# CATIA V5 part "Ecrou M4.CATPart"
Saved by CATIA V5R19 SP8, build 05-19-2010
Part number: Nut M4
Definition: Nut M4
Nomenclature: 71002
Material "Chrome": density 7190 kg/m3, Young's modulus 7e+10 Pa, Poisson ratio 0.3, thermal expansion 6.2e-06 1/K
Bounding box of the stored display mesh (mm): x -4.041 to 4.041, y -3.525 to 3.525, z 0 to 3.2
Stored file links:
  D:\Documents\1_Travail\1 - ac-limoges.fr\ac-limoges.fr\Emmanuel Maynard - STI2D_Turgot\1 - IT-I2D\Activités_IT_Première\IT_3_Abris_bus\Maquettes numériques\Abribus_eleve\Ecrou M4.CATPart
  C:\Program Files\Dassault Systemes\B19\win_b64\reffiles\standard\MetricThickPitch.txt
  C:\Program Files\Dassault Systemes\B19\win_b64\startup\materials\French\Catalog.CATMaterial
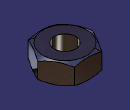
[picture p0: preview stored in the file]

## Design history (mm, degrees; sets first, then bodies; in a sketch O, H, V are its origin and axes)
AxisSystem1: origin (0, 0, 0), X (1, 0, 0), Y (0, 1, 0), Z (0, 0, 1)
Body1 (main body), material "Chrome"
  Sketch1 on XY plane of AxisSystem1, origin (0, 0, 0), H (1, 0, 0), V (0, 1, 0)
    point P1 (1.9763, -3.5253)
    point P2 (4.0411, -0.0511)
    point P3 (2.0649, 3.4741)
    point P4 (-1.9763, 3.5253)
    point P5 (-4.0411, 0.0511)
    point P6 (-2.0649, -3.4741)
    point P7 (3.0087, -1.7882)
    line L1 (1.9763, -3.5253) -> (4.0411, -0.0511)
    line L2 (4.0411, -0.0511) -> (2.0649, 3.4741)
    line L3 (2.0649, 3.4741) -> (-1.9763, 3.5253)
    line L4 (-1.9763, 3.5253) -> (-4.0411, 0.0511)
    line L5 (-4.0411, 0.0511) -> (-2.0649, -3.4741)
    line L6 (-2.0649, -3.4741) -> (1.9763, -3.5253)
    construction line L7 (0, 0) -> (3.0087, -1.7882)
    construction circle A1 centre (0, 0) radius 4.0415
    construction arc A2 centre (-4.0411, 0.0511) radius 4.0415 from (-1.9763, 3.5253) to (-2.0649, -3.4741) cw
    construction arc A3 centre (4.0411, -0.0511) radius 4.0415 from (2.0649, 3.4741) to (1.9763, -3.5253) ccw
    distance L1 L4 = 7
    coincidence: A1 P1, A1 P2, A1 P3, A1 P4, A1 P5, A1 P6, A2 O, A3 O
    midpoint: P7 L1
  Pad1: profile Sketch1, direction (0, 0, 1), length 3.2
  Sketch2 on YZ plane of AxisSystem1, origin (0, 0, 0), H (0, 1, 0), V (0, 0, 1)
    point P1 (3.3003, 3.2)
    line L1 (3.3003, 3.2) -> (6.0716, 1.6)
    line L2 (6.0716, 1.6) -> (3.3003, 0)
    point P3 (3.3003, 0)
    reference intersected line E1 (-3.5003, 3.2) -> (3.5003, 3.2) from end face of Pad1
    reference intersected line E2 (3.5003, 3.2) -> (3.5003, 0) from face of Pad1 from Sketch1.L3
    reference intersected line E3 (3.5003, 0) -> (-3.5003, 0) from start face of Pad1
    reference intersected line E4 (3.5003, 3.2) -> (3.5003, 0) from face of Pad1 from Sketch1.L3
    axis line L3 (0, -1.396) -> (0, 5.2618)
    point P4 (0, -1.396)
    reference projected line E5 (3.5253, 3.2) -> (0.0511, 3.2) from edge [face of Pad1 from Sketch1.L4 | end face of Pad1]
    reference intersected line E6 (3.5003, 0) -> (-3.5003, 0) from start face of Pad1
    distance P1 E2 = 0.2
    distance P3 E4 = 0.2
    angle L1 E5 = 30
    angle L2 E6 = 30
    coincidence: P1 E1, P3 E3, P4 V
    vertical: L3 V
  Groove1: profile Sketch2, axis Sketch2.L3, angle 360
  Sketch3 on end face of Pad1, origin (0.276, 0.3809, 3.2), H (1, 0, 0), V (0, 1, 0)
    point P1 (-0.276, -0.3809)
    reference projected point E1 (-0.276, -0.3809) from vertex [YZ plane of AxisSystem1 | ZX plane of AxisSystem1 | XY plane of AxisSystem1]
    coincidence: P1 E1
  Hole1: placed by Sketch3, at (0, 0, 3.2) direction (0, 0, -1), diameter 3.242, through (limit type 3), threaded "M4", thread diameter 4, thread depth 3.2, pitch 0.7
